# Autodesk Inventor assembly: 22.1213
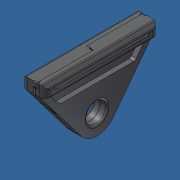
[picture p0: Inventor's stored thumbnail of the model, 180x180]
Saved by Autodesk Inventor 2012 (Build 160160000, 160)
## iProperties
Created: 2017-10
Part Number: 22.1213
Document SubType Name: Assembly
Designer: Admin
Description: TOOL HANGER H
Stock Number: 22.1213 TOOL HANGER H
Author: Admin
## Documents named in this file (2)
- C:\Andys Backup Data\ANDY'S INVENTOR\INVENTOR LIBRARIES\PARTS LIBRARY\WORKSTATION\22.1213 TOOL HANGER H.iam
- C:\Andys Backup Data\ANDY'S INVENTOR\INVENTOR LIBRARIES\PARTS LIBRARY\WORKSTATION\SUBCOMPONENTS\22.1213_1 TOOL HANGER H HALF.ipt
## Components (2 placed, 1 different names)
1. 22.1213_1 TOOL HANGER H HALF:1 — Mate:1, Flush:1, Flush:2
2. 22.1213_1 TOOL HANGER H HALF:2 — Mate:1, Flush:1, Flush:2
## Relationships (3: Flush 2, Mate 1)
- Mate:1: 22.1213_1 TOOL HANGER H HALF:1 ↔ 22.1213_1 TOOL HANGER H HALF:2
- Flush:1: 22.1213_1 TOOL HANGER H HALF:1 ↔ 22.1213_1 TOOL HANGER H HALF:2
- Flush:2: 22.1213_1 TOOL HANGER H HALF:1 ↔ 22.1213_1 TOOL HANGER H HALF:2
